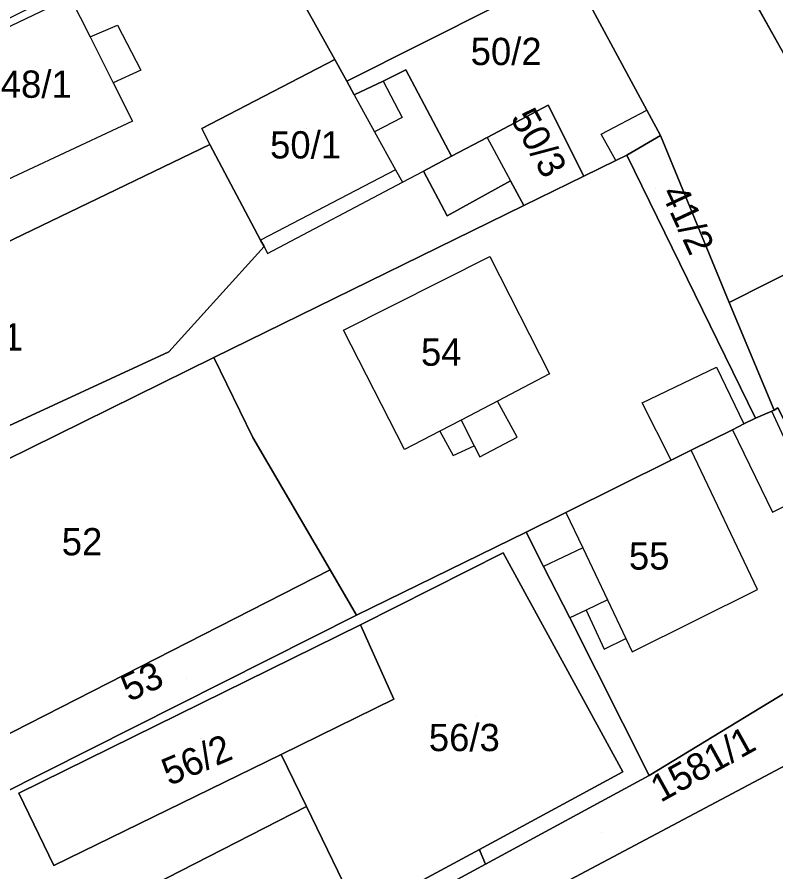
# Model space of a CAD drawing. Extents: x -263943 to -261149, y -1236934 to -1230686.
# Drawn here: x -262894.4 to -262838.8, y -1235694.2 to -1235631.6 of the extents above; entities that cross this region are included whole.
import ezdxf

# ---------------------------------------------------------------- set-up
doc = ezdxf.new("R2010")
doc.units = 0
for name, color, linetype in [('body_kn', 7, 'Continuous'), ('kladpar_druhypozemkov', 7, 'Continuous'), ('kladpar_hranice', 7, 'Continuous'), ('kladpar_parcelnecisla', 7, 'Continuous'), ('kladpar_plochy', 7, 'Continuous'), ('zappar_hrandruhpozemk', 7, 'Continuous')]:
    doc.layers.add(name, color=color, linetype=linetype)

msp = doc.modelspace()

# ---------------------------------------------------------------- linework, layer by layer
at = {"layer": 'body_kn'}
for p, q in [((-262887.04, -1235632.15), (-262887.04, -1235632.15)), ((-262889.06, -1235633.01), (-262889.06, -1235633.01)), ((-262871.12, -1235634.68), (-262871.12, -1235634.68)), ((-262871.12, -1235634.68), (-262871.12, -1235634.68)), ((-262885.35, -1235635.46), (-262885.35, -1235635.46)), ((-262865.91, -1235635.44), (-262865.91, -1235635.44)), ((-262887.36, -1235636.39), (-262887.36, -1235636.39)), ((-262887.36, -1235636.39), (-262887.36, -1235636.39)), ((-262870.24, -1235636.27), (-262870.24, -1235636.27)), ((-262867.58, -1235636.25), (-262867.58, -1235636.25)), ((-262867.58, -1235636.25), (-262867.58, -1235636.25)), ((-262869.69, -1235637.27), (-262869.69, -1235637.27)), ((-262869.69, -1235637.27), (-262869.69, -1235637.27)), ((-262855.48, -1235638.02), (-262855.48, -1235638.02)), ((-262848.25, -1235638.39), (-262848.25, -1235638.39)), ((-262866.18, -1235638.92), (-262866.18, -1235638.92)), ((-262885.96, -1235639.2), (-262885.96, -1235639.2)), ((-262880.87, -1235639.72), (-262880.87, -1235639.72)), ((-262868.2, -1235639.97), (-262868.2, -1235639.97)), ((-262859.96, -1235640.39), (-262859.96, -1235640.39)), ((-262859.96, -1235640.39), (-262859.96, -1235640.39)), ((-262851.58, -1235640.15), (-262851.58, -1235640.15)), ((-262847.25, -1235640.25), (-262847.25, -1235640.25)), ((-262880.28, -1235640.91), (-262880.28, -1235640.91)), ((-262849.72, -1235641.69), (-262849.72, -1235641.69)), ((-262849.72, -1235641.69), (-262849.72, -1235641.69)), ((-262862.57, -1235641.77), (-262862.57, -1235641.77)), ((-262850.51, -1235642.08), (-262850.51, -1235642.08)), ((-262850.51, -1235642.08), (-262850.51, -1235642.08)), ((-262866.66, -1235642.77), (-262866.66, -1235642.77)), ((-262864.61, -1235642.85), (-262864.61, -1235642.85)), ((-262858.25, -1235643.56), (-262858.25, -1235643.56)), ((-262858.25, -1235643.56), (-262858.25, -1235643.56)), ((-262852.85, -1235643.23), (-262852.85, -1235643.23)), ((-262866.16, -1235643.67), (-262866.16, -1235643.67)), ((-262866.16, -1235643.67), (-262866.16, -1235643.67)), ((-262857.26, -1235645.39), (-262857.26, -1235645.39)), ((-262862.89, -1235646.14), (-262862.89, -1235646.14)), ((-262876.56, -1235647.92), (-262876.56, -1235647.92)), ((-262876.31, -1235648.39), (-262876.31, -1235648.39)), ((-262876.31, -1235648.39), (-262876.31, -1235648.39)), ((-262876.06, -1235648.9), (-262876.06, -1235648.9)), ((-262859.76, -1235649.12), (-262859.76, -1235649.12)), ((-262842.2, -1235652.49), (-262842.2, -1235652.49)), ((-262870.47, -1235654.52), (-262870.47, -1235654.52)), ((-262870.47, -1235654.52), (-262870.47, -1235654.52)), ((-262883.3, -1235656.1), (-262883.3, -1235656.1)), ((-262883.3, -1235656.1), (-262883.3, -1235656.1)), ((-262879.99, -1235656.53), (-262879.99, -1235656.53)), ((-262843.14, -1235657.24), (-262843.14, -1235657.24)), ((-262855.37, -1235657.71), (-262855.37, -1235657.71)), ((-262859.2, -1235659.72), (-262859.2, -1235659.72)), ((-262859.2, -1235659.72), (-262859.2, -1235659.72)), ((-262848.59, -1235659.85), (-262848.59, -1235659.85)), ((-262839.09, -1235660.47), (-262839.09, -1235660.47)), ((-262838.91, -1235660.39), (-262838.91, -1235660.39)), ((-262861.86, -1235661.11), (-262861.86, -1235661.11)), ((-262861.86, -1235661.11), (-262861.86, -1235661.11)), ((-262840.27, -1235660.98), (-262840.27, -1235660.98)), ((-262840.27, -1235660.98), (-262840.27, -1235660.98)), ((-262841.12, -1235661.4), (-262841.12, -1235661.4)), ((-262841.12, -1235661.4), (-262841.12, -1235661.4)), ((-262863.41, -1235661.92), (-262863.41, -1235661.92)), ((-262857.76, -1235662.37), (-262857.76, -1235662.37)), ((-262841.97, -1235661.82), (-262841.97, -1235661.82)), ((-262841.97, -1235661.82), (-262841.97, -1235661.82)), ((-262877.12, -1235662.4), (-262877.12, -1235662.4)), ((-262860.9, -1235663), (-262860.9, -1235663)), ((-262866, -1235663.28), (-262866, -1235663.28)), ((-262845, -1235663.33), (-262845, -1235663.33)), ((-262862.44, -1235663.71), (-262862.44, -1235663.71)), ((-262860.48, -1235663.81), (-262860.48, -1235663.81)), ((-262846.46, -1235664.05), (-262846.46, -1235664.05)), ((-262846.46, -1235664.05), (-262846.46, -1235664.05)), ((-262854.18, -1235667.88), (-262854.18, -1235667.88)), ((-262854.18, -1235667.88), (-262854.18, -1235667.88)), ((-262839.02, -1235667.86), (-262839.02, -1235667.86)), ((-262857.1, -1235669.33), (-262857.1, -1235669.33)), ((-262852.94, -1235670.49), (-262852.94, -1235670.49)), ((-262858.77, -1235670.86), (-262858.77, -1235670.86)), ((-262871.46, -1235672.09), (-262871.46, -1235672.09)), ((-262855.83, -1235671.84), (-262855.83, -1235671.84)), ((-262840.14, -1235673.54), (-262840.14, -1235673.54)), ((-262851.13, -1235674.29), (-262851.13, -1235674.29)), ((-262851.13, -1235674.29), (-262851.13, -1235674.29)), ((-262869.52, -1235675.41), (-262869.52, -1235675.41)), ((-262852.7, -1235675.05), (-262852.7, -1235675.05)), ((-262852.7, -1235675.05), (-262852.7, -1235675.05)), ((-262869.23, -1235676.12), (-262869.23, -1235676.12)), ((-262853.9, -1235675.62), (-262853.9, -1235675.62)), ((-262849.78, -1235677.14), (-262849.78, -1235677.14)), ((-262849.78, -1235677.14), (-262849.78, -1235677.14)), ((-262851.36, -1235677.92), (-262851.36, -1235677.92)), ((-262849.32, -1235678.1), (-262849.32, -1235678.1)), ((-262866.79, -1235681.59), (-262866.79, -1235681.59)), ((-262875.06, -1235685.63), (-262875.06, -1235685.63)), ((-262875.06, -1235685.63), (-262875.06, -1235685.63)), ((-262850, -1235686.92), (-262850, -1235686.92)), ((-262848.07, -1235687.18), (-262848.07, -1235687.18)), ((-262894.28, -1235688.48), (-262894.28, -1235688.48)), ((-262894.28, -1235688.48), (-262894.28, -1235688.48)), ((-262873.19, -1235689.46), (-262873.19, -1235689.46)), ((-262860.51, -1235692.6), (-262860.51, -1235692.6)), ((-262860.45, -1235692.76), (-262860.45, -1235692.76)), ((-262860.08, -1235693.69), (-262860.08, -1235693.69)), ((-262891.72, -1235693.77), (-262891.72, -1235693.77))]:
    msp.add_line(p, q, dxfattribs=at)
at = {"layer": 'kladpar_druhypozemkov'}
for p, q in [((-262858.01, -1235633.38), (-262858.01, -1235633.38)), ((-262893.06, -1235635.18), (-262893.06, -1235635.18)), ((-262873.21, -1235639.73), (-262873.21, -1235639.73)), ((-262855.11, -1235640.93), (-262855.11, -1235640.93)), ((-262847.61, -1235644.13), (-262847.61, -1235644.13)), ((-262863.81, -1235655.03), (-262863.81, -1235655.03)), ((-262889.91, -1235668.68), (-262889.91, -1235668.68)), ((-262848.21, -1235669.93), (-262848.21, -1235669.93)), ((-262882.01, -1235680.08), (-262882.01, -1235680.08)), ((-262860.74, -1235682.75), (-262860.74, -1235682.75)), ((-262880.93, -1235684.48), (-262880.93, -1235684.48)), ((-262851.53, -1235691.38), (-262851.53, -1235691.38))]:
    msp.add_line(p, q, dxfattribs=at)
at = {"layer": 'kladpar_hranice'}
for points in [[(-262836.53, -1235649.64), (-262842.2, -1235652.49), (-262847.25, -1235640.25), (-262848.25, -1235638.39), (-262853.83, -1235628.01), (-262860.66, -1235614.49), (-262868.42, -1235600.38), (-262859.8, -1235594.3), (-262854.67, -1235603.02), (-262841.85, -1235627.71), (-262831.14, -1235646.92), (-262831.79, -1235647.25), (-262836.53, -1235649.64)], [(-262871.12, -1235634.68), (-262873.11, -1235631.09), (-262877.23, -1235622.87), (-262860.66, -1235614.49), (-262853.83, -1235628.01), (-262870.24, -1235636.27), (-262871.12, -1235634.68)], [(-262871.12, -1235634.68), (-262880.87, -1235639.72), (-262880.28, -1235640.91), (-262915.27, -1235657.76), (-262917.41, -1235653.53), (-262895.14, -1235643.5), (-262899.72, -1235634.51), (-262899.95, -1235634.06), (-262877.84, -1235623.18), (-262877.23, -1235622.87), (-262873.11, -1235631.09), (-262871.12, -1235634.68)], [(-262807.43, -1235666.43), (-262818.31, -1235671.58), (-262819.12, -1235670.03), (-262831.14, -1235646.92), (-262841.85, -1235627.71), (-262838.01, -1235625.69), (-262837.02, -1235627.38), (-262830.98, -1235623.75), (-262817.81, -1235647.56), (-262807.61, -1235666.11)], [(-262849.72, -1235641.69), (-262850.51, -1235642.08), (-262852.85, -1235643.23), (-262855.48, -1235638.02), (-262859.96, -1235640.39), (-262862.57, -1235641.77), (-262865.91, -1235635.44), (-262867.58, -1235636.25), (-262869.69, -1235637.27), (-262870.24, -1235636.27), (-262853.83, -1235628.01), (-262848.25, -1235638.39), (-262847.25, -1235640.25), (-262849.72, -1235641.69)], [(-262867.58, -1235636.25), (-262865.91, -1235635.44), (-262862.57, -1235641.77), (-262864.61, -1235642.85), (-262862.89, -1235646.14), (-262858.25, -1235643.56), (-262857.26, -1235645.39), (-262879.99, -1235656.53), (-262908.72, -1235670.7), (-262911.21, -1235665.77), (-262904.46, -1235665.88), (-262883.3, -1235656.1), (-262876.31, -1235648.39), (-262876.56, -1235647.92), (-262880.28, -1235640.91), (-262880.87, -1235639.72), (-262871.12, -1235634.68), (-262870.24, -1235636.27), (-262869.69, -1235637.27), (-262867.58, -1235636.25)], [(-262858.25, -1235643.56), (-262862.89, -1235646.14), (-262864.61, -1235642.85), (-262862.57, -1235641.77), (-262859.96, -1235640.39), (-262855.48, -1235638.02), (-262852.85, -1235643.23), (-262857.26, -1235645.39), (-262858.25, -1235643.56)], [(-262840.27, -1235660.98), (-262849.72, -1235641.69), (-262847.25, -1235640.25), (-262842.2, -1235652.49), (-262838.91, -1235660.39), (-262839.09, -1235660.47), (-262840.27, -1235660.98)], [(-262883.3, -1235656.1), (-262904.46, -1235665.88), (-262911.21, -1235665.77), (-262915.27, -1235657.76), (-262880.28, -1235640.91), (-262876.56, -1235647.92), (-262876.31, -1235648.39), (-262883.3, -1235656.1)], [(-262840.27, -1235660.98), (-262841.12, -1235661.4), (-262841.97, -1235661.82), (-262845, -1235663.33), (-262846.46, -1235664.05), (-262854.18, -1235667.88), (-262857.1, -1235669.33), (-262869.52, -1235675.41), (-262871.46, -1235672.09), (-262877.12, -1235662.4), (-262879.99, -1235656.53), (-262857.26, -1235645.39), (-262852.85, -1235643.23), (-262850.51, -1235642.08), (-262849.72, -1235641.69), (-262840.27, -1235660.98)], [(-262818.31, -1235671.58), (-262823.75, -1235674.36), (-262830.47, -1235676.46), (-262838.65, -1235660.22), (-262838.91, -1235660.39), (-262842.2, -1235652.49), (-262836.53, -1235649.64), (-262831.79, -1235647.25), (-262831.14, -1235646.92), (-262819.12, -1235670.03), (-262818.31, -1235671.58)], [(-262900.55, -1235686.94), (-262908.72, -1235670.7), (-262879.99, -1235656.53), (-262877.12, -1235662.4), (-262871.46, -1235672.09), (-262900.55, -1235686.94)], [(-262841.12, -1235661.4), (-262840.27, -1235660.98), (-262839.09, -1235660.47), (-262838.91, -1235660.39), (-262838.65, -1235660.22), (-262830.47, -1235676.46), (-262848.07, -1235687.18), (-262853.9, -1235675.62), (-262855.83, -1235671.84), (-262857.1, -1235669.33), (-262854.18, -1235667.88), (-262846.46, -1235664.05), (-262845, -1235663.33), (-262841.97, -1235661.82), (-262841.12, -1235661.4)], [(-262875.06, -1235685.63), (-262873.19, -1235689.46), (-262893.67, -1235699.93), (-262895.58, -1235696.68), (-262896.06, -1235695.86), (-262898.91, -1235690.2), (-262869.52, -1235675.41), (-262857.1, -1235669.33), (-262855.83, -1235671.84), (-262853.9, -1235675.62), (-262848.07, -1235687.18), (-262860.08, -1235693.69), (-262860.45, -1235692.76), (-262860.51, -1235692.6), (-262850, -1235686.92), (-262858.77, -1235670.86), (-262869.23, -1235676.12), (-262894.28, -1235688.48), (-262891.72, -1235693.77), (-262875.06, -1235685.63)], [(-262875.06, -1235685.63), (-262866.79, -1235681.59), (-262869.23, -1235676.12), (-262858.77, -1235670.86), (-262850, -1235686.92), (-262860.51, -1235692.6), (-262869.35, -1235697.38), (-262873.19, -1235689.46), (-262875.06, -1235685.63)], [(-262900.55, -1235686.94), (-262871.46, -1235672.09), (-262869.52, -1235675.41), (-262898.91, -1235690.2), (-262900.55, -1235686.94)], [(-262894.28, -1235688.48), (-262869.23, -1235676.12), (-262866.79, -1235681.59), (-262875.06, -1235685.63), (-262891.72, -1235693.77), (-262894.28, -1235688.48)], [(-262837.63, -1235686.2), (-262873.68, -1235705.35), (-262881.75, -1235709.66), (-262883.12, -1235710.93), (-262883.97, -1235712.03), (-262884.48, -1235713.64), (-262884.74, -1235715.76), (-262890.32, -1235705.64), (-262883.19, -1235705.83), (-262875.96, -1235702.29), (-262860.08, -1235693.69), (-262848.07, -1235687.18), (-262830.47, -1235676.46)], [(-262856.62, -1235707.27), (-262882.46, -1235720.94), (-262884.74, -1235715.76), (-262884.48, -1235713.64), (-262883.97, -1235712.03), (-262883.12, -1235710.93), (-262881.75, -1235709.66), (-262873.68, -1235705.35), (-262837.63, -1235686.2), (-262833.41, -1235695.12), (-262842.25, -1235699.76), (-262856.62, -1235707.27)], [(-262893.67, -1235699.93), (-262873.19, -1235689.46), (-262869.35, -1235697.38), (-262860.51, -1235692.6), (-262860.45, -1235692.76), (-262860.08, -1235693.69), (-262875.96, -1235702.29), (-262883.19, -1235705.83), (-262890.32, -1235705.64), (-262893.67, -1235699.93)]]:
    msp.add_lwpolyline(points, dxfattribs=at)
at = {"layer": 'kladpar_plochy'}
msp.add_line((-262831.14, -1235646.92), (-262841.85, -1235627.71), dxfattribs=at)
for points in [[(-262836.53, -1235649.64), (-262842.2, -1235652.49), (-262847.25, -1235640.25), (-262848.25, -1235638.39), (-262853.83, -1235628.01), (-262860.66, -1235614.49), (-262868.42, -1235600.38), (-262859.8, -1235594.3), (-262854.67, -1235603.02), (-262841.85, -1235627.71), (-262831.14, -1235646.92), (-262831.79, -1235647.25)], [(-262871.12, -1235634.68), (-262873.11, -1235631.09), (-262877.23, -1235622.87), (-262860.66, -1235614.49), (-262853.83, -1235628.01), (-262870.24, -1235636.27)], [(-262871.12, -1235634.68), (-262880.87, -1235639.72), (-262880.28, -1235640.91), (-262915.27, -1235657.76), (-262917.41, -1235653.53), (-262895.14, -1235643.5), (-262899.72, -1235634.51), (-262899.95, -1235634.06), (-262877.84, -1235623.18), (-262877.23, -1235622.87), (-262873.11, -1235631.09)], [(-262849.72, -1235641.69), (-262850.51, -1235642.08), (-262852.85, -1235643.23), (-262855.48, -1235638.02), (-262859.96, -1235640.39), (-262862.57, -1235641.77), (-262865.91, -1235635.44), (-262867.58, -1235636.25), (-262869.69, -1235637.27), (-262870.24, -1235636.27), (-262853.83, -1235628.01), (-262848.25, -1235638.39), (-262847.25, -1235640.25)], [(-262867.58, -1235636.25), (-262865.91, -1235635.44), (-262862.57, -1235641.77), (-262864.61, -1235642.85), (-262862.89, -1235646.14), (-262858.25, -1235643.56), (-262857.26, -1235645.39), (-262879.99, -1235656.53), (-262908.72, -1235670.7), (-262911.21, -1235665.77), (-262904.46, -1235665.88), (-262883.3, -1235656.1), (-262876.31, -1235648.39), (-262876.56, -1235647.92), (-262880.28, -1235640.91), (-262880.87, -1235639.72), (-262871.12, -1235634.68), (-262870.24, -1235636.27), (-262869.69, -1235637.27)], [(-262858.25, -1235643.56), (-262862.89, -1235646.14), (-262864.61, -1235642.85), (-262862.57, -1235641.77), (-262859.96, -1235640.39), (-262855.48, -1235638.02), (-262852.85, -1235643.23), (-262857.26, -1235645.39)], [(-262840.27, -1235660.98), (-262849.72, -1235641.69), (-262847.25, -1235640.25), (-262842.2, -1235652.49), (-262838.91, -1235660.39), (-262839.09, -1235660.47)], [(-262883.3, -1235656.1), (-262904.46, -1235665.88), (-262911.21, -1235665.77), (-262915.27, -1235657.76), (-262880.28, -1235640.91), (-262876.56, -1235647.92), (-262876.31, -1235648.39)], [(-262840.27, -1235660.98), (-262841.12, -1235661.4), (-262841.97, -1235661.82), (-262845, -1235663.33), (-262846.46, -1235664.05), (-262854.18, -1235667.88), (-262857.1, -1235669.33), (-262869.52, -1235675.41), (-262871.46, -1235672.09), (-262877.12, -1235662.4), (-262879.99, -1235656.53), (-262857.26, -1235645.39), (-262852.85, -1235643.23), (-262850.51, -1235642.08), (-262849.72, -1235641.69)], [(-262818.31, -1235671.58), (-262823.75, -1235674.36), (-262830.47, -1235676.46), (-262838.65, -1235660.22), (-262838.91, -1235660.39), (-262842.2, -1235652.49), (-262836.53, -1235649.64), (-262831.79, -1235647.25), (-262831.14, -1235646.92), (-262819.12, -1235670.03)], [(-262900.55, -1235686.94), (-262908.72, -1235670.7), (-262879.99, -1235656.53), (-262877.12, -1235662.4), (-262871.46, -1235672.09)], [(-262841.12, -1235661.4), (-262840.27, -1235660.98), (-262839.09, -1235660.47), (-262838.91, -1235660.39), (-262838.65, -1235660.22), (-262830.47, -1235676.46), (-262848.07, -1235687.18), (-262853.9, -1235675.62), (-262855.83, -1235671.84), (-262857.1, -1235669.33), (-262854.18, -1235667.88), (-262846.46, -1235664.05), (-262845, -1235663.33), (-262841.97, -1235661.82)], [(-262875.06, -1235685.63), (-262873.19, -1235689.46), (-262893.67, -1235699.93), (-262895.58, -1235696.68), (-262896.06, -1235695.86), (-262898.91, -1235690.2), (-262869.52, -1235675.41), (-262857.1, -1235669.33), (-262855.83, -1235671.84), (-262853.9, -1235675.62), (-262848.07, -1235687.18), (-262860.08, -1235693.69), (-262860.45, -1235692.76), (-262860.51, -1235692.6), (-262850, -1235686.92), (-262858.77, -1235670.86), (-262869.23, -1235676.12), (-262894.28, -1235688.48), (-262891.72, -1235693.77)], [(-262875.06, -1235685.63), (-262866.79, -1235681.59), (-262869.23, -1235676.12), (-262858.77, -1235670.86), (-262850, -1235686.92), (-262860.51, -1235692.6), (-262869.35, -1235697.38), (-262873.19, -1235689.46)], [(-262900.55, -1235686.94), (-262871.46, -1235672.09), (-262869.52, -1235675.41), (-262898.91, -1235690.2)], [(-262894.28, -1235688.48), (-262869.23, -1235676.12), (-262866.79, -1235681.59), (-262875.06, -1235685.63), (-262891.72, -1235693.77)], [(-262856.62, -1235707.27), (-262882.46, -1235720.94), (-262884.74, -1235715.76), (-262884.48, -1235713.64), (-262883.97, -1235712.03), (-262883.12, -1235710.93), (-262881.75, -1235709.66), (-262873.68, -1235705.35), (-262837.63, -1235686.2), (-262833.41, -1235695.12), (-262842.25, -1235699.76)], [(-262893.67, -1235699.93), (-262873.19, -1235689.46), (-262869.35, -1235697.38), (-262860.51, -1235692.6), (-262860.45, -1235692.76), (-262860.08, -1235693.69), (-262875.96, -1235702.29), (-262883.19, -1235705.83), (-262890.32, -1235705.64)]]:
    msp.add_lwpolyline(points, close=True, dxfattribs=at)
msp.add_lwpolyline([(-262837.63, -1235686.2), (-262873.68, -1235705.35), (-262881.75, -1235709.66), (-262883.12, -1235710.93), (-262883.97, -1235712.03), (-262884.48, -1235713.64), (-262884.74, -1235715.76), (-262890.32, -1235705.64), (-262883.19, -1235705.83), (-262875.96, -1235702.29), (-262860.08, -1235693.69), (-262848.07, -1235687.18), (-262830.47, -1235676.46)], dxfattribs=at)
at = {"layer": 'zappar_hrandruhpozemk'}
for p, q in [((-262889.06, -1235633.01), (-262887.36, -1235636.39)), ((-262887.36, -1235636.39), (-262885.96, -1235639.2)), ((-262851.58, -1235640.15), (-262848.25, -1235638.39)), ((-262885.96, -1235639.2), (-262895.14, -1235643.5)), ((-262859.96, -1235640.39), (-262858.25, -1235643.56)), ((-262850.51, -1235642.08), (-262851.58, -1235640.15)), ((-262866.66, -1235642.77), (-262876.56, -1235647.92)), ((-262866.66, -1235642.77), (-262866.16, -1235643.67)), ((-262866.16, -1235643.67), (-262864.61, -1235642.85)), ((-262876.06, -1235648.9), (-262866.16, -1235643.67)), ((-262876.31, -1235648.39), (-262876.06, -1235648.9)), ((-262848.59, -1235659.85), (-262843.14, -1235657.24)), ((-262843.14, -1235657.24), (-262841.12, -1235661.4)), ((-262846.46, -1235664.05), (-262848.59, -1235659.85)), ((-262836.3, -1235666.51), (-262839.09, -1235660.47)), ((-262841.97, -1235661.82), (-262839.02, -1235667.86)), ((-262840.14, -1235673.54), (-262845, -1235663.33)), ((-262839.02, -1235667.86), (-262836.3, -1235666.51)), ((-262854.18, -1235667.88), (-262852.94, -1235670.49)), ((-262852.94, -1235670.49), (-262855.83, -1235671.84))]:
    msp.add_line(p, q, dxfattribs=at)
for points in [[(-262899.72, -1235634.51), (-262890.51, -1235630.1), (-262889.06, -1235633.01)], [(-262889.06, -1235633.01), (-262887.04, -1235632.15), (-262885.35, -1235635.46), (-262887.36, -1235636.39)], [(-262867.58, -1235636.25), (-262866.18, -1235638.92), (-262868.2, -1235639.97)], [(-262869.69, -1235637.27), (-262868.2, -1235639.97), (-262866.66, -1235642.77)], [(-262870.47, -1235654.52), (-262859.76, -1235649.12), (-262855.37, -1235657.71), (-262859.2, -1235659.72)], [(-262863.41, -1235661.92), (-262866, -1235663.28), (-262870.47, -1235654.52)], [(-262859.2, -1235659.72), (-262861.86, -1235661.11), (-262863.41, -1235661.92)], [(-262861.86, -1235661.11), (-262860.9, -1235663), (-262860.48, -1235663.81), (-262857.76, -1235662.37), (-262859.2, -1235659.72)], [(-262863.41, -1235661.92), (-262862.44, -1235663.71), (-262860.9, -1235663)], [(-262852.94, -1235670.49), (-262851.13, -1235674.29), (-262849.78, -1235677.14)], [(-262849.78, -1235677.14), (-262849.32, -1235678.1), (-262840.14, -1235673.54)], [(-262851.13, -1235674.29), (-262852.7, -1235675.05), (-262853.9, -1235675.62)], [(-262852.7, -1235675.05), (-262851.36, -1235677.92), (-262849.78, -1235677.14)]]:
    msp.add_lwpolyline(points, dxfattribs=at)

# ---------------------------------------------------------------- texts
at = {"layer": 'kladpar_parcelnecisla'}
for s, p in [('50/2', (-262861.161, -1235635.08)), ('48/1', (-262895.61, -1235637.48)), ('50/1', (-262875.865, -1235641.93)), ('51', (-262896.944, -1235656.03)), ('54', (-262864.803, -1235657.13)), ('52', (-262891.14, -1235671.03)), ('55', (-262849.558, -1235672.08)), ('56/3', (-262864.226, -1235685.39))]:
    msp.add_text(s, height=2, dxfattribs=at).set_placement(p)
for s, rotation, p in [('50/3', 299, (-262858.291, -1235638.966)), ('41/2', 295, (-262847.244, -1235644.44)), ('53', 25, (-262886.199, -1235681.802)), ('56/2', 23, (-262883.261, -1235687.957)), ('1581/1', 29, (-262847.239, -1235689.192))]:
    msp.add_text(s, height=2, rotation=rotation, dxfattribs=at).set_placement(p)

doc.saveas('drawing.dxf')
